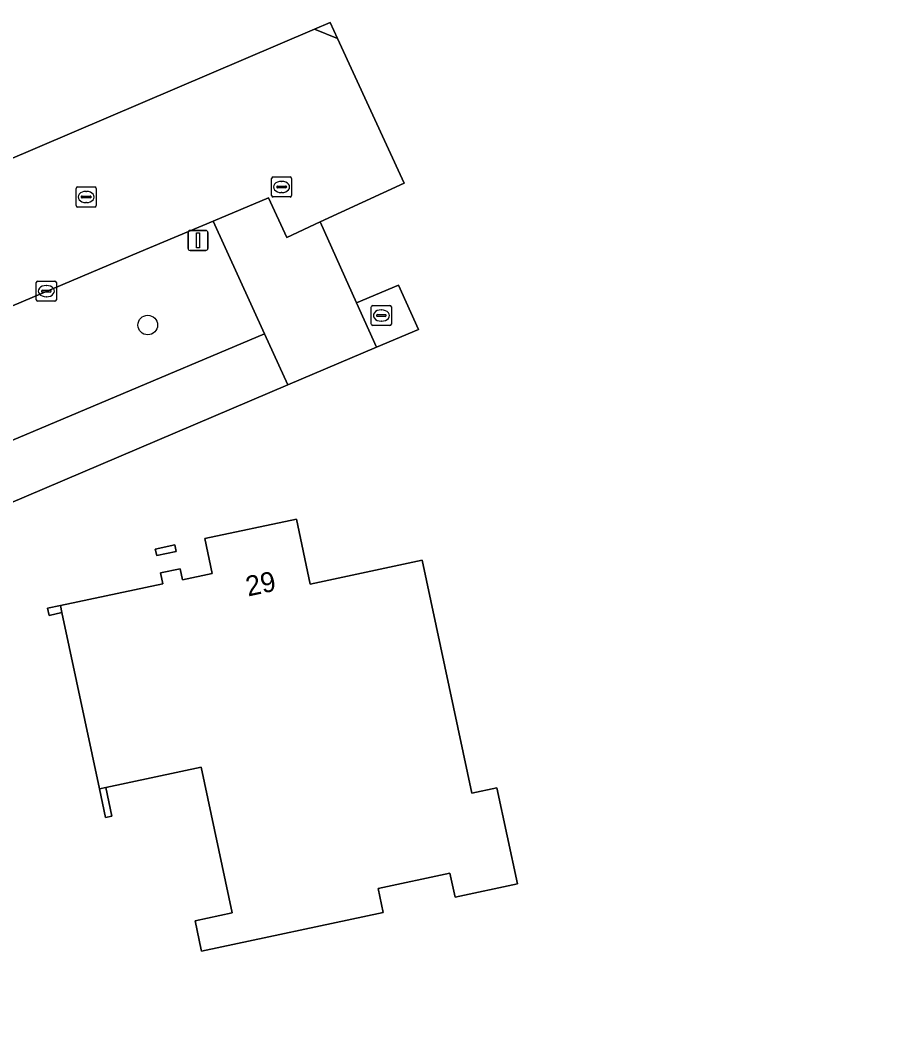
# Model space of a CAD drawing. Extents: x 162417 to 163722, y 384268 to 385417.
# Drawn here: x 163210.8 to 163254.9, y 384770.5 to 384821.1 of the extents above; entities that cross this region are included whole.
import ezdxf

# ---------------------------------------------------------------- set-up
doc = ezdxf.new("R2010")
doc.units = 0
for name, color, linetype in [('IMGEO_Berm_groen', 7, 'Continuous'), ('IMGEO_Boom', 7, 'Continuous'), ('IMGEO_Brandkraan', 7, 'Continuous'), ('IMGEO_Erf', 7, 'Continuous'), ('IMGEO_Groenvoorziening', 7, 'Continuous'), ('IMGEO_Hek', 7, 'Continuous'), ('IMGEO_Kolk', 7, 'Continuous'), ('IMGEO_Lichtmast', 7, 'Continuous'), ('IMGEO_Muur', 7, 'Continuous'), ('IMGEO_Pand', 7, 'Continuous'), ('IMGEO_Pand_nummerreeks', 7, 'Continuous'), ('IMGEO_Rijbaan_lokaal_gesloten', 7, 'Continuous'), ('IMGEO_Rioolput', 7, 'Continuous'), ('IMGEO_Voetpad_open', 7, 'Continuous')]:
    doc.layers.add(name, color=color, linetype=linetype)

msp = doc.modelspace()

# ---------------------------------------------------------------- linework, layer by layer
at = {"layer": 'IMGEO_Berm_groen'}
msp.add_lwpolyline([(163222.984, 384805.457), (163220.41, 384811.089), (163216.72, 384809.538), (163190.562, 384798.467), (163190.259, 384798.333), (163191.508, 384792.188), (163191.759, 384792.294)], close=True, dxfattribs=at)
at = {"layer": 'IMGEO_Boom'}
msp.add_circle((163217.153, 384805.902), 0.489, dxfattribs=at)
at = {"layer": 'IMGEO_Brandkraan'}
for p, q in [((163228.308, 384805.952), (163228.308, 384806.804)), ((163228.383, 384806.878), (163229.235, 384806.878)), ((163228.796, 384806.658), (163228.821, 384806.658)), ((163229.309, 384806.804), (163229.309, 384805.952)), ((163228.567, 384806.372), (163228.567, 384806.384)), ((163229.005, 384806.335), (163228.607, 384806.335)), ((163228.61, 384806.421), (163229.008, 384806.421)), ((163228.819, 384806.098), (163228.794, 384806.098)), ((163229.051, 384806.384), (163229.051, 384806.372)), ((163229.235, 384805.878), (163228.383, 384805.878))]:
    msp.add_line(p, q, dxfattribs=at)
for points in [[(163228.308, 384805.952), (163228.308, 384806.804)], [(163228.383, 384806.878), (163229.235, 384806.878)], [(163229.309, 384806.804), (163229.309, 384805.952)], [(163229.235, 384805.878), (163228.383, 384805.878)]]:
    msp.add_lwpolyline(points, dxfattribs=at)
for centre, radius, start, end in [((163228.385, 384806.802), 0.0765, 91.552, 178.448), ((163228.385, 384806.802), 0.0765, 91.552, 178.448), ((163229.233, 384806.802), 0.0765, 1.552, 88.448), ((163229.233, 384806.802), 0.0765, 1.552, 88.448), ((163228.607, 384806.381), 0.0403, 85.8775, 175.7526), ((163228.604, 384806.371), 0.0366, 178.938, 274.7102), ((163229.008, 384806.378), 0.043, 264.8664, 352.4533), ((163229.012, 384806.383), 0.0386, 1.7309, 96.639), ((163228.385, 384805.954), 0.0765, 181.552, 268.448), ((163228.385, 384805.954), 0.0765, 181.552, 268.448), ((163229.233, 384805.954), 0.0765, 271.552, 358.448), ((163229.233, 384805.954), 0.0765, 271.552, 358.448)]:
    msp.add_arc(centre, radius, start, end, dxfattribs=at)
for centre, major_axis, ratio, start_param, end_param in [((163228.795, 384806.378), (-0.387, 0.002), 0.722429, 4.712389, 7.853982), ((163228.82, 384806.378), (-0.39, 0.002), 0.717154, 1.570796, 4.712389)]:
    msp.add_ellipse(centre, major_axis=major_axis, ratio=ratio, start_param=start_param, end_param=end_param, dxfattribs=at)
at = {"layer": 'IMGEO_Erf'}
msp.add_lwpolyline([(163175.984, 384894.871), (163189.317, 384805.604), (163189.37, 384805.252), (163225.47, 384820.661), (163226.246, 384820.995), (163226.612, 384820.203), (163229.945, 384812.987), (163225.751, 384811.048), (163227.566, 384807.013), (163229.658, 384807.895), (163230.655, 384805.678), (163228.563, 384804.796), (163224.144, 384802.92), (163192.437, 384789.411), (163200.664, 384750), (163215.633, 384678.291), (163252.312, 384685.775), (163256.147, 384686.557), (163258.646, 384687.067), (163309.002, 384702.202), (163311.14, 384702.845), (163432.284, 384738.586)], dxfattribs=at)
for points in [[(163226.612, 384820.203), (163226.246, 384820.995), (163225.47, 384820.661)], [(163215.056, 384782.822), (163215.363, 384781.384), (163215.05, 384781.317), (163214.743, 384782.755), (163212.869, 384791.55), (163212.23, 384791.413), (163212.155, 384791.767), (163212.794, 384791.903), (163217.902, 384792.992), (163217.787, 384793.528), (163218.765, 384793.736), (163218.883, 384793.178), (163220.369, 384793.494), (163219.995, 384795.243), (163224.572, 384796.219), (163225.264, 384792.973), (163230.842, 384794.162), (163233.32, 384782.536), (163234.573, 384782.803), (163235.593, 384778.013), (163232.484, 384777.351), (163232.23, 384778.543), (163228.646, 384777.779), (163228.899, 384776.589), (163219.838, 384774.658), (163219.823, 384774.728), (163219.516, 384776.17), (163221.365, 384776.564), (163219.815, 384783.836)], [(163218.51, 384794.927), (163218.579, 384794.604), (163217.601, 384794.395), (163217.532, 384794.718)]]:
    msp.add_lwpolyline(points, close=True, dxfattribs=at)
at = {"layer": 'IMGEO_Groenvoorziening'}
msp.add_lwpolyline([(163230.655, 384805.678), (163229.658, 384807.895), (163227.566, 384807.013), (163228.563, 384804.796)], close=True, dxfattribs=at)
at = {"layer": 'IMGEO_Hek'}
msp.add_lwpolyline([(163225.47, 384820.661), (163226.612, 384820.203)], dxfattribs=at)
at = {"layer": 'IMGEO_Kolk'}
for p, q in [((163223.331, 384812.367), (163223.331, 384813.219)), ((163223.406, 384813.293), (163224.258, 384813.293)), ((163224.332, 384813.219), (163224.332, 384812.367)), ((163223.59, 384812.787), (163223.59, 384812.799)), ((163224.028, 384812.75), (163223.63, 384812.75)), ((163223.633, 384812.836), (163224.031, 384812.836)), ((163223.819, 384813.073), (163223.844, 384813.073)), ((163224.074, 384812.799), (163224.074, 384812.787)), ((163224.258, 384812.293), (163223.406, 384812.293)), ((163223.842, 384812.513), (163223.817, 384812.513)), ((163211.669, 384808.094), (163212.521, 384808.094)), ((163211.594, 384807.168), (163211.594, 384808.02)), ((163211.853, 384807.588), (163211.853, 384807.6)), ((163211.896, 384807.637), (163212.294, 384807.637)), ((163212.082, 384807.874), (163212.107, 384807.874)), ((163212.337, 384807.6), (163212.337, 384807.588)), ((163212.595, 384808.02), (163212.595, 384807.168)), ((163212.521, 384807.094), (163211.669, 384807.094)), ((163212.291, 384807.551), (163211.893, 384807.551)), ((163212.105, 384807.314), (163212.08, 384807.314))]:
    msp.add_line(p, q, dxfattribs=at)
for points in [[(163223.331, 384812.367), (163223.331, 384813.219)], [(163223.406, 384813.293), (163224.258, 384813.293)], [(163224.332, 384813.219), (163224.332, 384812.367)], [(163224.258, 384812.293), (163223.406, 384812.293)], [(163211.669, 384808.094), (163212.521, 384808.094)], [(163211.594, 384807.168), (163211.594, 384808.02)], [(163212.595, 384808.02), (163212.595, 384807.168)], [(163212.521, 384807.094), (163211.669, 384807.094)]]:
    msp.add_lwpolyline(points, dxfattribs=at)
for centre, radius, start, end in [((163223.408, 384813.217), 0.0765, 91.552, 178.448), ((163223.408, 384813.217), 0.0765, 91.552, 178.448), ((163224.256, 384813.217), 0.0765, 1.552, 88.448), ((163224.256, 384813.217), 0.0765, 1.552, 88.448), ((163223.63, 384812.796), 0.0403, 85.8775, 175.7526), ((163223.627, 384812.786), 0.0366, 178.938, 274.7102), ((163224.031, 384812.793), 0.043, 264.8664, 352.4533), ((163224.035, 384812.798), 0.0386, 1.7309, 96.639), ((163223.408, 384812.369), 0.0765, 181.552, 268.448), ((163223.408, 384812.369), 0.0765, 181.552, 268.448), ((163224.256, 384812.369), 0.0765, 271.552, 358.448), ((163224.256, 384812.369), 0.0765, 271.552, 358.448), ((163211.671, 384808.018), 0.0765, 91.552, 178.448), ((163211.671, 384808.018), 0.0765, 91.552, 178.448), ((163212.519, 384808.018), 0.0765, 1.552, 88.448), ((163212.519, 384808.018), 0.0765, 1.552, 88.448), ((163211.893, 384807.597), 0.0403, 85.8775, 175.7526), ((163211.89, 384807.587), 0.0366, 178.938, 274.7102), ((163212.294, 384807.594), 0.043, 264.8664, 352.4533), ((163212.298, 384807.599), 0.0386, 1.7309, 96.639), ((163211.671, 384807.17), 0.0765, 181.552, 268.448), ((163211.671, 384807.17), 0.0765, 181.552, 268.448), ((163212.519, 384807.17), 0.0765, 271.552, 358.448), ((163212.519, 384807.17), 0.0765, 271.552, 358.448)]:
    msp.add_arc(centre, radius, start, end, dxfattribs=at)
for centre, major_axis, ratio, start_param, end_param in [((163223.818, 384812.793), (-0.387, 0.002), 0.722429, 4.712389, 7.853982), ((163223.843, 384812.793), (-0.39, 0.002), 0.717154, 1.570796, 4.712389), ((163212.081, 384807.594), (-0.387, 0.002), 0.722429, 4.712389, 7.853982), ((163212.106, 384807.594), (-0.39, 0.002), 0.717154, 1.570796, 4.712389)]:
    msp.add_ellipse(centre, major_axis=major_axis, ratio=ratio, start_param=start_param, end_param=end_param, dxfattribs=at)
at = {"layer": 'IMGEO_Lichtmast'}
for p, q in [((163219.263, 384810.623), (163220.053, 384810.623)), ((163220.053, 384810.623), (163219.263, 384810.623)), ((163219.163, 384809.723), (163219.163, 384810.523)), ((163219.163, 384810.523), (163219.163, 384809.723)), ((163220.153, 384810.523), (163220.153, 384809.723)), ((163220.153, 384809.723), (163220.153, 384810.523)), ((163220.053, 384809.623), (163219.263, 384809.623)), ((163219.263, 384809.623), (163220.053, 384809.623))]:
    msp.add_line(p, q, dxfattribs=at)
msp.add_lwpolyline([(163219.583, 384810.498), (163219.733, 384810.498), (163219.733, 384809.748), (163219.583, 384809.748), (163219.583, 384810.498)], dxfattribs=at)
for centre, start, end in [((163219.263, 384810.523), 90, 180), ((163219.263, 384810.523), 90, 180), ((163220.053, 384810.523), 0, 90), ((163220.053, 384810.523), 360, 90), ((163219.263, 384809.723), 180, 270), ((163219.263, 384809.723), 180, 270), ((163220.053, 384809.723), 270, 0), ((163220.053, 384809.723), 270, 0)]:
    msp.add_arc(centre, 0.1, start, end, dxfattribs=at)
at = {"layer": 'IMGEO_Muur'}
for points in [[(163212.794, 384791.903), (163212.155, 384791.767), (163212.23, 384791.413), (163212.869, 384791.55)], [(163215.056, 384782.822), (163214.743, 384782.755), (163215.05, 384781.317), (163215.363, 384781.384)]]:
    msp.add_lwpolyline(points, close=True, dxfattribs=at)
at = {"layer": 'IMGEO_Pand'}
for points in [[(163230.842, 384794.162), (163225.264, 384792.973), (163224.572, 384796.219), (163219.995, 384795.243), (163220.369, 384793.494), (163218.883, 384793.178), (163218.765, 384793.736), (163217.787, 384793.528), (163217.902, 384792.992), (163212.794, 384791.903), (163212.869, 384791.55), (163214.743, 384782.755), (163215.056, 384782.822), (163219.815, 384783.836), (163221.365, 384776.564), (163219.516, 384776.17), (163219.823, 384774.728), (163219.838, 384774.658), (163228.899, 384776.589), (163228.646, 384777.779), (163232.23, 384778.543), (163232.484, 384777.351), (163235.593, 384778.013), (163234.573, 384782.803), (163233.32, 384782.536)], [(163218.51, 384794.927), (163217.532, 384794.718), (163217.601, 384794.395), (163218.579, 384794.604)]]:
    msp.add_lwpolyline(points, close=True, dxfattribs=at)
at = {"layer": 'IMGEO_Rijbaan_lokaal_gesloten'}
for points in [[(163216.72, 384809.538), (163220.41, 384811.089), (163223.174, 384812.257), (163224.089, 384810.279), (163225.751, 384811.048), (163229.945, 384812.987), (163226.612, 384820.203), (163225.47, 384820.661), (163189.37, 384805.252), (163189.317, 384805.604), (163186.712, 384804.512), (163186.458, 384804.456)], [(163187.011, 384796.942), (163187.865, 384797.272), (163190.259, 384798.333), (163190.562, 384798.467), (163216.72, 384809.538)]]:
    msp.add_lwpolyline(points, dxfattribs=at)
at = {"layer": 'IMGEO_Rioolput'}
for p, q in [((163213.581, 384811.867), (163213.581, 384812.719)), ((163213.656, 384812.793), (163214.508, 384812.793)), ((163214.582, 384812.719), (163214.582, 384811.867)), ((163213.84, 384812.287), (163213.84, 384812.299)), ((163214.278, 384812.25), (163213.88, 384812.25)), ((163213.883, 384812.336), (163214.281, 384812.336)), ((163214.069, 384812.573), (163214.094, 384812.573)), ((163214.324, 384812.299), (163214.324, 384812.287)), ((163214.508, 384811.793), (163213.656, 384811.793)), ((163214.092, 384812.013), (163214.067, 384812.013))]:
    msp.add_line(p, q, dxfattribs=at)
for points in [[(163213.581, 384811.867), (163213.581, 384812.719)], [(163213.656, 384812.793), (163214.508, 384812.793)], [(163214.582, 384812.719), (163214.582, 384811.867)], [(163214.508, 384811.793), (163213.656, 384811.793)]]:
    msp.add_lwpolyline(points, dxfattribs=at)
for centre, radius, start, end in [((163213.658, 384812.717), 0.0765, 91.552, 178.448), ((163213.658, 384812.717), 0.0765, 91.552, 178.448), ((163214.506, 384812.717), 0.0765, 1.552, 88.448), ((163214.506, 384812.717), 0.0765, 1.552, 88.448), ((163213.88, 384812.296), 0.0403, 85.8775, 175.7526), ((163213.877, 384812.286), 0.0366, 178.938, 274.7102), ((163214.281, 384812.293), 0.043, 264.8664, 352.4533), ((163214.285, 384812.298), 0.0386, 1.7309, 96.639), ((163213.658, 384811.869), 0.0765, 181.552, 268.448), ((163213.658, 384811.869), 0.0765, 181.552, 268.448), ((163214.506, 384811.869), 0.0765, 271.552, 358.448), ((163214.506, 384811.869), 0.0765, 271.552, 358.448)]:
    msp.add_arc(centre, radius, start, end, dxfattribs=at)
for centre, major_axis, ratio, start_param, end_param in [((163214.068, 384812.293), (-0.387, 0.002), 0.722429, 4.712389, 7.853982), ((163214.093, 384812.293), (-0.39, 0.002), 0.717154, 1.570796, 4.712389)]:
    msp.add_ellipse(centre, major_axis=major_axis, ratio=ratio, start_param=start_param, end_param=end_param, dxfattribs=at)
at = {"layer": 'IMGEO_Voetpad_open'}
msp.add_lwpolyline([(163220.41, 384811.089), (163222.984, 384805.457), (163224.144, 384802.92), (163228.563, 384804.796), (163227.566, 384807.013), (163225.751, 384811.048), (163224.089, 384810.279), (163223.174, 384812.257)], close=True, dxfattribs=at)
msp.add_lwpolyline([(163215.633, 384678.291), (163200.664, 384750), (163192.437, 384789.411), (163224.144, 384802.92), (163222.984, 384805.457), (163191.759, 384792.294), (163191.508, 384792.188), (163190.259, 384798.333), (163187.865, 384797.272), (163189.155, 384791.225), (163184.397, 384789.202), (163184.207, 384789.121), (163184.787, 384786.144), (163185.02, 384786.243), (163189.733, 384788.253), (163195.494, 384760.643), (163196.211, 384757.311), (163197.729, 384750), (163201.604, 384731.339), (163201.827, 384730.264), (163202.624, 384726.782), (163212.911, 384677.77)], dxfattribs=at)

# ---------------------------------------------------------------- texts
at = {"layer": 'IMGEO_Pand_nummerreeks'}
msp.add_text('29', height=1, rotation=12.0378, dxfattribs=at).set_placement((163222.159, 384792.351))

doc.saveas('drawing.dxf')
